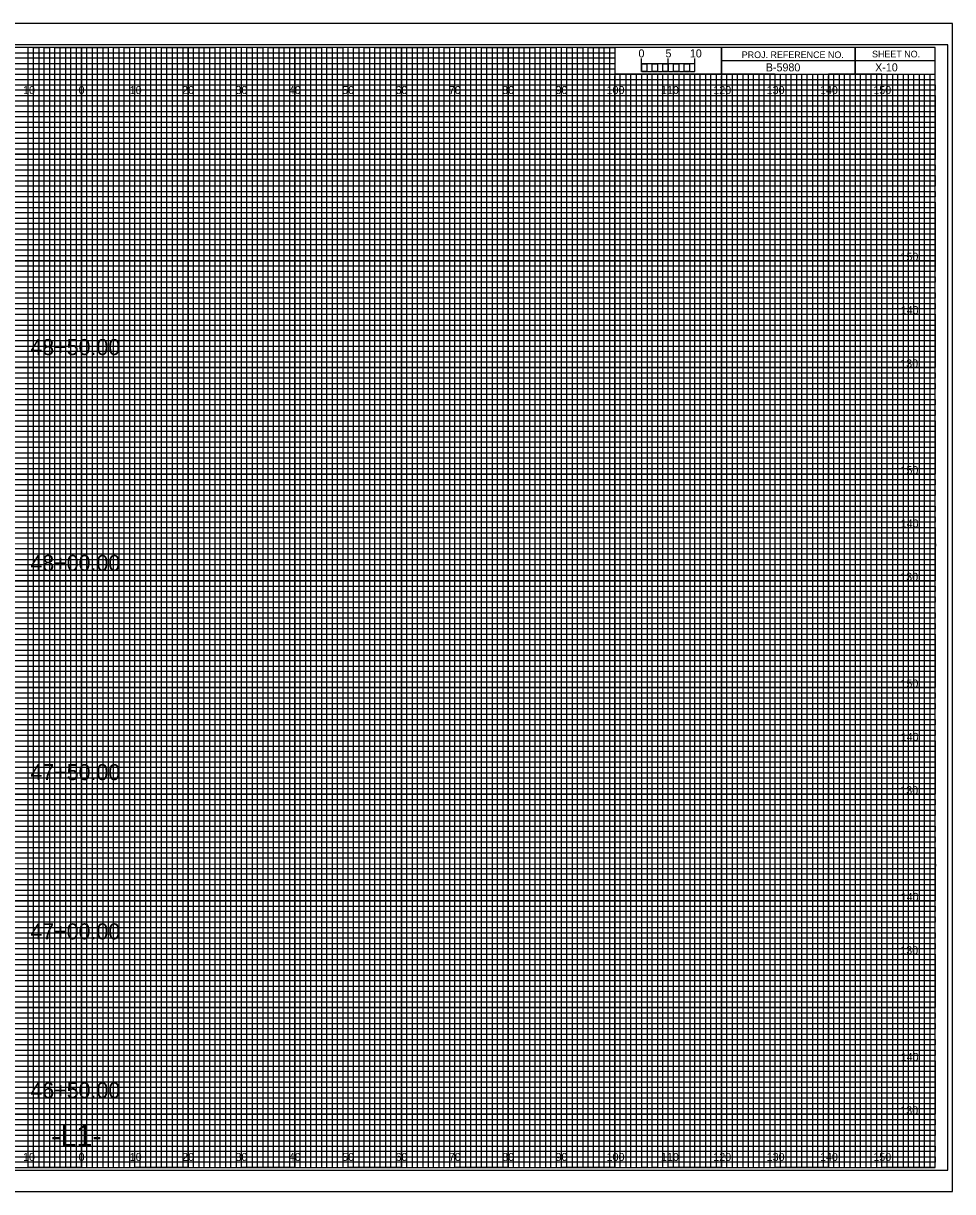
# Model space of a CAD drawing. Extents: x -13 to 323, y -5 to 3294.
# Drawn here: x 149.1 to 323.3, y 1975.5 to 2194.5 of the extents above; entities that cross this region are included whole.
import ezdxf

# ---------------------------------------------------------------- set-up
doc = ezdxf.new("R2010")
doc.units = 0
for name, color, linetype in [('Prop XS Alignment Label', 7, 'Continuous'), ('Prop XS Bar Scale Labels', 7, 'Continuous'), ('Prop XS Elevation Labels', 7, 'Continuous'), ('Prop XS Offset Labels', 7, 'Continuous'), ('Prop XS Project Number', 7, 'Continuous'), ('Prop XS Sheet Number', 7, 'Continuous'), ('Prop XS Station Labels', 7, 'Continuous'), ('Sheet Cross Section CELL', 7, 'Continuous'), ('Sheet Cross Section Grid Major CELL', 7, 'Continuous'), ('Sheet Cross Section Grid Middle CELL', 7, 'Continuous'), ('Sheet Cross Section Grid Minor 1 CELL', 7, 'Continuous'), ('Sheet Cross Section Grid Minor 2 CELL', 7, 'Continuous'), ('Sheet Cross Section Scale CELL', 7, 'Continuous'), ('Sheet Cutting Line CELL', 7, 'Continuous'), ('Sheet DOT Grid CELL', 7, 'Continuous'), ('Sheet Plot Border Inside CELL', 7, 'Continuous'), ('Sheet Plot Border Outside CELL', 7, 'Continuous')]:
    doc.layers.add(name, color=color, linetype=linetype)

msp = doc.modelspace()

# ---------------------------------------------------------------- linework, layer by layer
at = {"layer": 'Sheet Cross Section CELL'}
for p, q in [((305, 2190), (305, 2185)), ((305, 2185), (305, 2190)), ((280, 2187.5), (280, 2185)), ((320, 2187.49), (280, 2187.49)), ((280, 2185), (320, 2185))]:
    msp.add_line(p, q, dxfattribs=at)
for points in [[(320, 2190), (0, 2190), (0, 1980), (320, 1980)], [(280, 2190), (260, 2190), (260, 2185.03), (280, 2185.03)], [(320, 2190), (280, 2190), (280, 2185), (320, 2185)]]:
    msp.add_lwpolyline(points, close=True, dxfattribs=at)
at = {"layer": 'Sheet Cross Section Grid Major CELL'}
for p, q in [((150, 2190), (140, 2190)), ((150, 1980), (150, 2190)), ((170, 2190), (160, 2190)), ((160, 2190), (160, 1980)), ((170, 1980), (170, 2190)), ((190, 2190), (180, 2190)), ((180, 2190), (180, 1980)), ((190, 1980), (190, 2190)), ((210, 2190), (200, 2190)), ((200, 2190), (200, 1980)), ((210, 1980), (210, 2190)), ((230, 2190), (220, 2190)), ((220, 2190), (220, 1980)), ((230, 1980), (230, 2190)), ((250, 2190), (240, 2190)), ((240, 2190), (240, 1980)), ((250, 1980), (250, 2190)), ((260, 2190), (260, 1980)), ((270, 1980), (270, 2185)), ((290, 2185), (280, 2185)), ((280, 2185), (280, 1980)), ((290, 1980), (290, 2185)), ((310, 2185), (300, 2185)), ((300, 2185), (300, 1980)), ((310, 1980), (310, 2185)), ((160, 1980), (150, 1980)), ((180, 1980), (170, 1980)), ((200, 1980), (190, 1980)), ((220, 1980), (210, 1980)), ((240, 1980), (230, 1980)), ((260, 1980), (250, 1980)), ((280, 1980), (270, 1980)), ((300, 1980), (290, 1980)), ((320, 1980), (310, 1980)), ((320, 1980), (320, 1980))]:
    msp.add_line(p, q, dxfattribs=at)
for points in [[(0, 2180), (320, 2180), (320, 2170), (0, 2170)], [(0, 2160), (320, 2160), (320, 2150), (0, 2150)], [(0, 2140), (320, 2140), (320, 2130), (0, 2130)], [(0, 2120), (320, 2120), (320, 2110), (0, 2110)], [(0, 2100), (320, 2100), (320, 2090), (0, 2090)], [(0, 2080), (320, 2080), (320, 2070), (0, 2070)], [(0, 2060), (320, 2060), (320, 2050), (0, 2050)], [(0, 2040), (320, 2040), (320, 2030), (0, 2030)], [(0, 2020), (320, 2020), (320, 2010), (0, 2010)], [(0, 2000), (320, 2000), (320, 1990), (0, 1990)]]:
    msp.add_lwpolyline(points, dxfattribs=at)
at = {"layer": 'Sheet Cross Section Grid Middle CELL'}
for points in [[(145, 1980), (155, 1980), (155, 2190), (165, 2190), (165, 1980), (175, 1980), (175, 2190), (185, 2190), (185, 1980), (195, 1980), (195, 2190), (205, 2190), (205, 1980), (215, 1980), (215, 2190), (225, 2190), (225, 1980), (235, 1980), (235, 2190), (245, 2190), (245, 1980), (255, 1980), (255, 2190), (259.93, 2190), (260, 2190), (260, 2185), (264.99, 2185), (264.99, 1980), (275, 1980), (275, 2185), (285, 2185), (285, 1980), (295, 1980), (295, 2185), (305, 2185), (305, 1980), (315, 1980), (315, 2185)], [(0, 2185), (275, 2185)], [(0, 2165), (320, 2165), (320, 2175), (0, 2175)], [(0, 2145), (320, 2145), (320, 2155), (0, 2155)], [(0, 2125), (320, 2125), (320, 2135), (0, 2135)], [(0, 2105), (320, 2105), (320, 2115), (0, 2115)], [(0, 2085), (320, 2085), (320, 2095), (0, 2095)], [(0, 2065), (320, 2065), (320, 2075), (0, 2075)], [(0, 2045), (320, 2045), (320, 2055), (0, 2055)], [(0, 2025), (320, 2025), (320, 2035), (0, 2035)], [(0, 2005), (320, 2005), (320, 2015), (0, 2015)], [(0, 1985), (320, 1985), (320, 1995), (0, 1995)]]:
    msp.add_lwpolyline(points, dxfattribs=at)
at = {"layer": 'Sheet Cross Section Grid Minor 1 CELL'}
for p, q in [((0, 2189), (260, 2189)), ((260, 2187.98), (0, 2187.98)), ((260, 2189), (260, 2187.98)), ((0, 2187), (260, 2187)), ((260, 2185.89), (0, 2185.89)), ((260, 2187), (260, 2185.89)), ((0, 2184), (320, 2184))]:
    msp.add_line(p, q, dxfattribs=at)
for points in [[(0, 2183), (270, 2183), (320, 2183), (320, 2182), (0, 2182)], [(0, 2181), (320, 2181), (320, 2179), (0, 2179)], [(0, 2178), (320, 2178), (320, 2177), (0, 2176.98)], [(0, 2176), (320, 2176), (320, 2174), (0, 2174)], [(0, 2173), (320, 2173), (320, 2172), (0, 2172)], [(0, 2171), (320, 2171), (320, 2169), (0, 2169)], [(0, 2168), (320, 2168), (320, 2167), (0, 2167)], [(0, 2166), (320, 2166), (320, 2164), (0, 2164)], [(0, 2163), (320, 2163), (320, 2162), (0, 2162)], [(0, 2161), (320, 2161), (320, 2159), (0, 2159)], [(0, 2158), (320, 2158), (320, 2157), (0, 2157)], [(0, 2156), (320, 2156), (320, 2153.95), (320, 2153), (320, 2152), (0, 2152)], [(0, 2154), (320, 2154), (320, 2153), (0, 2153)], [(0, 2151), (320, 2151), (320, 2149), (0, 2149.03)], [(0, 2149.03), (320, 2149), (320, 2148), (0, 2148)], [(0, 2147), (320, 2147), (320, 2146), (0, 2146)], [(0, 2144), (320, 2144), (320, 2143), (0, 2143)], [(0, 2142), (320, 2142), (320, 2141), (0, 2141)], [(-0.07, 2138.89), (320, 2138.89), (320, 2137.88), (-0.07, 2137.88)], [(0, 2137), (320, 2137), (320, 2136), (0, 2136)], [(0, 2134), (320, 2134), (320, 2133), (0, 2133)], [(0, 2132), (320, 2132), (320, 2131), (0, 2131)], [(0, 2129), (320, 2129), (320, 2128), (0, 2128)], [(0, 2127), (320, 2127), (320, 2126), (0, 2126)], [(0, 2124), (320, 2124), (320, 2123), (0, 2123)], [(0, 2122), (320, 2122), (320, 2121), (0, 2121)], [(0, 2119), (320, 2119), (319.99, 2117.98), (0, 2118)], [(0, 2117), (320, 2117), (320, 2116), (0, 2116)], [(0, 2114), (320, 2114), (320, 2113), (0, 2113)], [(0, 2112), (320, 2112), (320, 2111), (0, 2111)], [(0, 2109), (320, 2109), (320, 2108), (0, 2108)], [(0, 2107), (320, 2107), (320, 2106), (0, 2106)], [(0, 2104), (320, 2104), (320, 2103), (0, 2103)], [(0, 2102), (320, 2102), (320, 2101), (0, 2101)], [(0, 2099), (320, 2099), (320, 2098), (0, 2098)], [(0, 2096.99), (320.07, 2096.91), (320, 2096), (0, 2096)], [(0, 2094), (320, 2094), (320, 2093), (0, 2093)], [(0, 2092), (320, 2092), (320, 2091), (0, 2091)], [(0, 2089), (320, 2089), (320, 2088), (0, 2088)], [(0, 2087), (320, 2087), (320, 2086), (0, 2086)], [(0, 2084), (320, 2084), (320, 2083), (0, 2083)], [(0, 2082), (320, 2082), (320, 2081), (0, 2081)], [(0, 2079), (320, 2079), (320, 2078), (0, 2078)], [(0, 2077), (320, 2077), (320, 2076), (0, 2076)], [(0, 2074), (320, 2074), (320, 2073), (0, 2073)], [(0, 2072), (320, 2072), (320, 2071), (0, 2071)], [(0, 2069), (320, 2069), (320, 2068), (0, 2068)], [(0, 2067), (320, 2067), (320, 2066), (0, 2066)], [(0, 2064), (320, 2064), (320, 2063), (0, 2063)], [(0, 2062), (320, 2062), (320, 2061), (0, 2061)], [(0, 2059), (320, 2059), (319.99, 2057.98), (0, 2058)], [(0, 2057), (320, 2057), (320, 2056), (0, 2056)], [(0, 2054), (320, 2054), (320, 2053), (0, 2053)], [(0, 2052), (320, 2052), (320, 2051), (0, 2051)], [(0, 2049), (320, 2049), (320, 2048), (0, 2048)], [(0, 2047), (320, 2047), (320, 2046), (0, 2046)], [(0, 2044), (320, 2044), (320, 2043), (0, 2043)], [(0, 2042), (320, 2042), (320, 2041), (0, 2041)], [(0, 2039), (320, 2039), (320, 2038), (0, 2038)], [(0, 2036.99), (320.07, 2036.91), (320, 2036), (0, 2036)], [(0, 2034), (320, 2034), (320, 2033), (0, 2033)], [(0, 2032), (320, 2032), (320, 2031), (0, 2031)], [(0, 2029), (320, 2029), (320, 2028), (0, 2028)], [(0, 2027), (320, 2027), (320, 2026), (0, 2026)], [(0, 2024), (320, 2024), (320, 2023), (0, 2023)], [(0, 2022), (320, 2022), (320, 2021), (0, 2021)], [(0, 2019), (320, 2019), (320, 2018), (0, 2018)], [(0, 2017), (320, 2017), (320, 2016), (0, 2016)], [(0, 2014), (320, 2014), (320, 2013), (0, 2013)], [(0, 2012), (320, 2012), (320, 2011), (0, 2011)], [(0, 2009), (320, 2009), (320, 2008), (0, 2008)], [(0, 2007), (320, 2007), (320, 2006), (0, 2006)], [(0, 2004), (320, 2004), (320, 2003), (0, 2003)], [(0, 2002), (320, 2002), (320, 2001), (0, 2001)], [(0, 1999), (320, 1999), (320, 1998), (0, 1998)], [(0, 1997), (320, 1997), (320, 1996), (0, 1996)], [(0, 1994), (320, 1994), (320, 1993), (0, 1993)], [(0, 1992), (320, 1992), (320, 1991), (0, 1991)], [(0, 1989), (320, 1989), (320, 1988), (0, 1988)], [(0, 1987), (320, 1987), (320, 1986), (0, 1986)], [(0, 1984), (320, 1984), (320, 1983), (0, 1983)], [(0, 1982), (320, 1982), (320, 1981), (0, 1981)]]:
    msp.add_lwpolyline(points, dxfattribs=at)
at = {"layer": 'Sheet Cross Section Grid Minor 2 CELL'}
for p, q in [((267, 2185), (266.01, 2185)), ((266.01, 2185), (266.01, 1980)), ((267, 1980), (267, 2185)), ((269, 2185), (268, 2185)), ((268, 2185), (268, 1980)), ((269, 1980), (269, 2185)), ((266.01, 1980), (265, 1980)), ((268, 1980), (267, 1980))]:
    msp.add_line(p, q, dxfattribs=at)
for points in [[(150, 1980), (151, 1980), (151, 2190), (152, 2190), (152, 1980)], [(152, 1980), (153, 1980), (153, 2190), (154, 2190), (154, 1980)], [(155, 1980), (156, 1980), (156, 2190), (157, 2190), (157, 1980)], [(157, 1980), (158, 1980), (158, 2190), (159, 2190), (159, 1980)], [(160, 1980), (161, 1980), (161, 2190), (162, 2190), (162, 1980)], [(162, 1980), (163, 1980), (163, 2190), (164, 2190), (164, 1980)], [(165, 1980), (166, 1980), (166, 2190), (167, 2190), (167, 1980)], [(167, 1980), (168, 1980), (168, 2190), (169, 2190), (169, 1980)], [(170, 1980), (171, 1980), (171, 2190), (172, 2190), (172, 1980)], [(172, 1980), (173, 1980), (173, 2190), (174, 2190), (174, 1980)], [(175, 1980), (176, 1980), (176, 2190), (177, 2190), (177, 1980)], [(177, 1980), (178, 1980), (178, 2190), (179, 2190), (179, 1980)], [(180, 1980), (181, 1980), (181, 2190), (182, 2190), (182, 1980)], [(182, 1980), (183, 1980), (183, 2190), (184, 2190), (184, 1980)], [(185, 1980), (186, 1980), (186, 2190), (187, 2190), (187, 1980)], [(187, 1980), (188, 1980), (188, 2190), (189, 2190), (189, 1980)], [(190, 1980), (191, 1980), (191, 2190), (192, 2190), (192, 1980)], [(192, 1980), (193, 1980), (193, 2190), (194, 2190), (194, 1980)], [(195, 1980), (196, 1980), (196, 2190), (197, 2190), (197, 1980)], [(197, 1980), (198, 1980), (198, 2190), (199, 2190), (199, 1980)], [(200, 1980), (201, 1980), (201, 2190), (202, 2190), (202, 1980)], [(202, 1980), (203, 1980), (203, 2190), (204, 2190), (204, 1980)], [(205, 1980), (206, 1980), (206, 2190), (207, 2190), (207, 1980)], [(207, 1980), (208, 1980), (208, 2190), (209, 2190), (209, 1980)], [(210, 1980), (211, 1980), (211, 2190), (212, 2190), (212, 1980)], [(212, 1980), (213, 1980), (213, 2190), (214, 2190), (214, 1980)], [(215, 1980), (216, 1980), (216, 2190), (217, 2190), (217, 1980)], [(217, 1980), (218, 1980), (218, 2190), (219, 2190), (219, 1980)], [(220, 1980), (221, 1980), (221, 2190), (222, 2190), (222, 1980)], [(222, 1980), (223, 1980), (223, 2190), (224, 2190), (224, 1980)], [(225, 1980), (226, 1980), (226, 2190), (227, 2190), (227, 1980)], [(227, 1980), (228, 1980), (228, 2190), (229, 2190), (229, 1980)], [(230, 1980), (231, 1980), (231, 2190), (232, 2190), (232, 1980)], [(232, 1980), (233, 1980), (233, 2190), (234, 2190), (234, 1980)], [(235, 1980), (236, 1980), (236, 2190), (237, 2190), (237, 1980)], [(237, 1980), (238, 1980), (238, 2190), (239, 2190), (239, 1980)], [(240, 1980), (241, 1980), (241, 2190), (242, 2190), (242, 1980)], [(242, 1980), (243, 1980), (243, 2190), (244, 2190), (244, 1980)], [(245, 1980), (246, 1980), (246, 2190), (247, 2190), (247, 1980)], [(247, 1980), (248, 1980), (248, 2190), (249, 2190), (249, 1980)], [(250, 1980), (251, 1980), (251, 2190), (252, 2190), (252, 1980)], [(252, 1980), (253, 1980), (253, 2190), (254, 2190), (254, 1980)], [(255, 1980), (256, 1980), (256, 2190), (257, 2190), (257, 1980)], [(257, 1980), (258, 1980), (258, 2190), (259, 2190), (259, 1980)], [(260, 1980), (261, 1980), (261, 2185), (262.02, 2185), (262.02, 1980)], [(262, 1980), (263, 1980), (263, 2185), (263.99, 2185), (263.99, 1980)], [(270, 1980), (270.98, 1980), (270.98, 2185), (272, 2185), (272, 1980)], [(272, 1980), (273, 1980), (273, 2185), (274.05, 2185), (274.05, 1980)], [(275, 1980), (276, 1980), (276, 2185), (277, 2185), (277, 1980)], [(277, 1980), (278, 1980), (278, 2185), (279, 2185), (279, 1980)], [(280, 1980), (281, 1980), (281, 2185), (282, 2185), (282, 1980)], [(282, 1980), (283, 1980), (283, 2185), (284, 2185), (284, 1980)], [(285, 1980), (286, 1980), (286, 2185), (287, 2185), (287, 1980)], [(287, 1980), (288, 1980), (288, 2185), (289, 2185), (289, 1980)], [(290, 1980), (291, 1980), (291, 2185), (292, 2185), (292, 1980)], [(292, 1980), (293, 1980), (293, 2185), (294, 2185), (294, 1980)], [(295, 1980), (296, 1980), (296, 2185), (297, 2185), (297, 1980)], [(297, 1980), (298, 1980), (298, 2185), (299, 2185), (299, 1980)], [(300, 1980), (301, 1980), (301, 2185), (302, 2185), (302, 1980)], [(302, 1980), (303, 1980), (303, 2185), (304, 2185), (304, 1980)], [(305, 1980), (306, 1980), (306, 2185), (307, 2185), (307, 1980)], [(307, 1980), (308, 1980), (308, 2185), (309, 2185), (309, 1980)], [(310, 1980), (311, 1980), (311, 2185), (312, 2185), (312, 1980)], [(312, 1980), (313, 1980), (313, 2185), (314, 2185), (314, 1980)], [(315, 1980), (316, 1980), (316, 2185), (317, 2185), (317, 1980)], [(317, 1980), (318, 1980), (318, 2185), (319, 2185), (319, 1980)]]:
    msp.add_lwpolyline(points, dxfattribs=at)
at = {"layer": 'Sheet Cross Section Scale CELL'}
for p, q in [((265, 2185.49), (265, 2187.9)), ((265, 2186.9), (265, 2187.9)), ((270, 2185.49), (270, 2187.9)), ((275, 2185.49), (275, 2187.9)), ((275, 2186.9), (275, 2187.9))]:
    msp.add_line(p, q, dxfattribs=at)
for points in [[(275, 2186.9), (265, 2186.9), (265, 2185.49), (275, 2185.49)], [(265, 2186.9), (266, 2186.9), (266, 2185.49), (265, 2185.49)], [(267, 2186.9), (268, 2186.9), (268, 2185.49), (267, 2185.49)], [(269, 2186.9), (270, 2186.9), (270, 2185.49), (269, 2185.49)], [(271, 2186.9), (272, 2186.9), (272, 2185.49), (271, 2185.49)], [(273, 2186.9), (274, 2186.9), (274, 2185.49), (273, 2185.49)]]:
    msp.add_lwpolyline(points, close=True, dxfattribs=at)
at = {"layer": 'Sheet Cutting Line CELL'}
for p, q in [((323.3, 2194.5), (-13.4, 2194.5)), ((-13.4, 1975.5), (323.3, 1975.5))]:
    msp.add_line(p, q, dxfattribs=at)
at = {"layer": 'Sheet DOT Grid CELL'}
for p, q in [((150, 1980), (150, 2190)), ((160, 1980), (160, 2190)), ((170, 1980), (170, 2190)), ((180, 1980), (180, 2190)), ((190, 1980), (190, 2190)), ((200, 1980), (200, 2190)), ((210, 1980), (210, 2190)), ((220, 1980), (220, 2190)), ((230, 1980), (230, 2190)), ((240, 1980), (240, 2190)), ((250, 1980), (250, 2190)), ((260, 1980), (260, 2184.69)), ((270, 1980), (270, 2184.69)), ((280, 1980), (280, 2184.69)), ((290, 1980), (290, 2184.69)), ((300, 1980), (300, 2184.69)), ((310, 1980), (310, 2184.69)), ((0, 2180), (320, 2180)), ((0, 2170), (320, 2170)), ((0, 2160), (320, 2160)), ((0, 2150), (320, 2150)), ((0, 2140), (320, 2140)), ((0, 2130), (320, 2130)), ((0, 2120), (320, 2120)), ((0, 2110), (320, 2110)), ((0, 2100), (320, 2100)), ((0, 2090), (320, 2090)), ((0, 2080), (320, 2080)), ((0, 2070), (320, 2070)), ((0, 2060), (320, 2060)), ((0, 2050), (320, 2050)), ((0, 2040), (320, 2040)), ((0, 2030), (320, 2030)), ((0, 2020), (320, 2020)), ((0, 2010), (320, 2010)), ((0, 2000), (320, 2000)), ((0, 1990), (320, 1990))]:
    msp.add_line(p, q, dxfattribs=at)
at = {"layer": 'Sheet Plot Border Inside CELL'}
msp.add_lwpolyline([(-10.8, 1979.5), (322.4, 1979.5), (322.4, 2190.5), (-10.8, 2190.5)], close=True, dxfattribs=at)
at = {"layer": 'Sheet Plot Border Outside CELL'}
msp.add_lwpolyline([(-13.4, 1975.5), (323.3, 1975.5), (323.3, 2194.5), (-13.4, 2194.5)], close=True, dxfattribs=at)

# ---------------------------------------------------------------- texts
at = {"layer": 'Prop XS Alignment Label'}
msp.add_text('-L1-', height=4, dxfattribs=at).set_placement((154.28, 1984))
at = {"layer": 'Prop XS Bar Scale Labels'}
for s, p in [('5', (269.47, 2188.12)), ('10', (274.04, 2188.12))]:
    msp.add_text(s, height=1.5, dxfattribs=at).set_placement(p)
at = {"layer": 'Prop XS Elevation Labels'}
for s, p in [('150', (313.52, 2150)), ('140', (313.57, 2140)), ('130', (313.49, 2130)), ('150', (313.52, 2110)), ('140', (313.57, 2100)), ('130', (313.49, 2090)), ('150', (313.52, 2070)), ('140', (313.57, 2060)), ('130', (313.49, 2050)), ('140', (313.57, 2030)), ('130', (313.49, 2020)), ('140', (313.57, 2000)), ('130', (313.49, 1990))]:
    msp.add_text(s, height=1.5, dxfattribs=at).set_placement(p)
at = {"layer": 'Prop XS Offset Labels'}
for s, p in [('10', (149.04, 2181.25)), ('0', (159.45, 2181.25)), ('0', (159.45, 2181.25)), ('10', (169.04, 2181.25)), ('20', (178.86, 2181.25)), ('30', (188.86, 2181.25)), ('40', (198.86, 2181.25)), ('50', (208.86, 2181.25)), ('60', (218.86, 2181.25)), ('70', (228.86, 2181.25)), ('80', (238.86, 2181.25)), ('90', (248.86, 2181.25)), ('100', (258.44, 2181.25)), ('110', (268.62, 2181.25)), ('120', (278.44, 2181.25)), ('130', (288.44, 2181.25)), ('140', (298.44, 2181.25)), ('150', (308.44, 2181.25)), ('10', (149.04, 1981.25)), ('0', (159.45, 1981.25)), ('0', (159.45, 1981.25)), ('10', (169.04, 1981.25)), ('20', (178.86, 1981.25)), ('30', (188.86, 1981.25)), ('40', (198.86, 1981.25)), ('50', (208.86, 1981.25)), ('60', (218.86, 1981.25)), ('70', (228.86, 1981.25)), ('80', (238.86, 1981.25)), ('90', (248.86, 1981.25)), ('100', (258.44, 1981.25)), ('110', (268.62, 1981.25)), ('120', (278.44, 1981.25)), ('130', (288.44, 1981.25)), ('140', (298.44, 1981.25)), ('150', (308.44, 1981.25))]:
    msp.add_text(s, height=1.5, dxfattribs=at).set_placement(p)
at = {"layer": 'Prop XS Project Number'}
msp.add_text('B-5980', height=1.5, dxfattribs=at).set_placement((288.28, 2185.5))
at = {"layer": 'Prop XS Sheet Number'}
msp.add_text('X-10', height=1.5, dxfattribs=at).set_placement((308.77, 2185.5))
at = {"layer": 'Prop XS Station Labels'}
for s, p in [('48+50.00', (150.41, 2132.32)), ('48+00.00', (150.41, 2091.85)), ('47+50.00', (150.41, 2052.64)), ('47+00.00', (150.41, 2022.79)), ('46+50.00', (150.41, 1993))]:
    msp.add_text(s, height=3, dxfattribs=at).set_placement(p)
at = {"layer": 'Sheet Cross Section CELL'}
for s, p in [('PROJ. REFERENCE NO.', (283.77, 2187.99)), ('SHEET NO.', (308.19, 2188.12))]:
    msp.add_text(s, height=1.25, dxfattribs=at).set_placement(p)
at = {"layer": 'Sheet Cross Section Scale CELL'}
msp.add_text('0', height=1.5, dxfattribs=at).set_placement((264.41, 2188.12))

doc.saveas('drawing.dxf')
